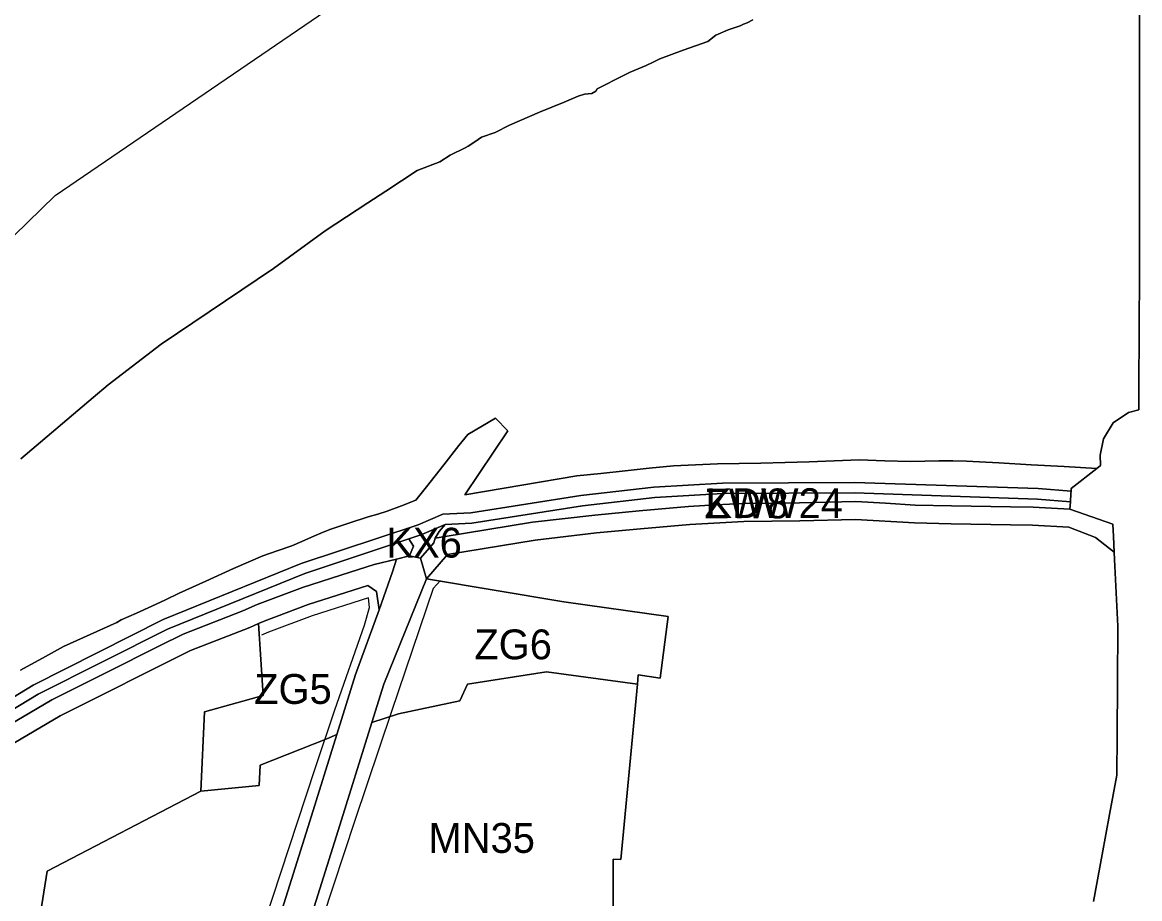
# Model space of a CAD drawing. Extents: x 7428841 to 7433518, y 5545054 to 5546840.
# Drawn here: x 7431568.9 to 7431943.4, y 5546261.6 to 5546555.3 of the extents above; entities that cross this region are included whole.
import ezdxf

# ---------------------------------------------------------------- set-up
doc = ezdxf.new("R2010")
doc.units = 0
for name, color, linetype in [('linie_rozgraniczajace', 7, 'Continuous'), ('linie_zabudowy_nieprzekraczalne', 7, 'Continuous'), ('oznaczenia_przeznaczen', 7, 'Continuous')]:
    doc.layers.add(name, color=color, linetype=linetype)

msp = doc.modelspace()

# ---------------------------------------------------------------- linework, layer by layer
at = {"layer": 'linie_rozgraniczajace'}
for points in [[(7431943.41, 5546570.58), (7431943.39, 5546479.9), (7431943.39, 5546471.91), (7431943.14, 5546432.52), (7431943.09, 5546425.43), (7431939.66, 5546424.55), (7431934.53, 5546421.02), (7431931.32, 5546415.69), (7431930.22, 5546410.24), (7431930.29, 5546406.73), (7431929.09, 5546405.79), (7431918.07, 5546406.42), (7431907.03, 5546407.04), (7431896.21, 5546407.64), (7431885.38, 5546408.23), (7431880.75, 5546408.3), (7431876.11, 5546408.38), (7431871.37, 5546408.22), (7431866.64, 5546408.06), (7431858, 5546408.34), (7431849.37, 5546408.62), (7431841, 5546408.3), (7431832.64, 5546407.97), (7431824.54, 5546407.78), (7431816.43, 5546407.6), (7431809.17, 5546407.44), (7431801.9, 5546407.29), (7431787.12, 5546406.69), (7431779.01, 5546405.84), (7431770.91, 5546404.99), (7431762.81, 5546404.14), (7431754.7, 5546403.29), (7431736.26, 5546400.2), (7431717.21, 5546396.99), (7431731.59, 5546418.42), (7431727.51, 5546422.65)], [(7431927.98, 5546260.72), (7431930.86, 5546276.41), (7431933.32, 5546289.8), (7431935.75, 5546303), (7431935.84, 5546316.43), (7431935.97, 5546333.93), (7431936.11, 5546352.9), (7431934.98, 5546375.22), (7431934.85, 5546377.76), (7431934.59, 5546382.97), (7431934.38, 5546387.09), (7431920.05, 5546392.14), (7431920.2, 5546394.64), (7431920.37, 5546397.33), (7431920.42, 5546398.14), (7431920.47, 5546399.05), (7431929.09, 5546405.79), (7431930.29, 5546406.73), (7431930.22, 5546410.24), (7431931.32, 5546415.69), (7431934.53, 5546421.02), (7431939.66, 5546424.55), (7431943.09, 5546425.43), (7431943.14, 5546432.52), (7431943.39, 5546471.91), (7431943.39, 5546479.9), (7431943.41, 5546570.58)], [(7431294.78, 5546263.35), (7431363.88, 5546310.19), (7431455.51, 5546382.62), (7431520.49, 5546439.04), (7431561.48, 5546479.2), (7431579.86, 5546497.22), (7431670.62, 5546559.16)], [(7431690.69, 5546498.7), (7431701.25, 5546505.59), (7431708.87, 5546508.49), (7431712.25, 5546510.78), (7431717.29, 5546513.26), (7431718.35, 5546513.78), (7431720.58, 5546515.26), (7431722.81, 5546516.75), (7431727.41, 5546518.34), (7431732.16, 5546520.78), (7431742.28, 5546525.11), (7431750.45, 5546528.51), (7431755.24, 5546530.47), (7431757.34, 5546531.16), (7431758.53, 5546531.28), (7431759.72, 5546531.41), (7431761.16, 5546532.24), (7431761.61, 5546532.95), (7431763.98, 5546534.17), (7431767.92, 5546536.19), (7431772.63, 5546538.61), (7431773.98, 5546539.15), (7431776.69, 5546540.25), (7431778.04, 5546540.8), (7431780.3, 5546541.9), (7431782.56, 5546543.01), (7431790.43, 5546545.88), (7431798.63, 5546548.86), (7431801.32, 5546551.01), (7431805.44, 5546552.71), (7431808.48, 5546553.78), (7431809.5, 5546554.14), (7431810.65, 5546554.63), (7431811.81, 5546555.11), (7431813.77, 5546556.09)], [(7431813.77, 5546556.09), (7431811.81, 5546555.11), (7431810.65, 5546554.63), (7431809.5, 5546554.14), (7431808.48, 5546553.78), (7431805.44, 5546552.71), (7431801.32, 5546551.01), (7431798.63, 5546548.86)], [(7431798.63, 5546548.86), (7431790.43, 5546545.88), (7431782.56, 5546543.01), (7431780.3, 5546541.9), (7431778.04, 5546540.8), (7431776.69, 5546540.25), (7431773.98, 5546539.15), (7431772.63, 5546538.61), (7431767.92, 5546536.19), (7431763.98, 5546534.17), (7431761.61, 5546532.95), (7431761.16, 5546532.24), (7431759.72, 5546531.41), (7431758.53, 5546531.28), (7431757.34, 5546531.16), (7431755.24, 5546530.47), (7431750.45, 5546528.51), (7431742.28, 5546525.11), (7431732.16, 5546520.78), (7431727.41, 5546518.34), (7431722.81, 5546516.75), (7431720.58, 5546515.26), (7431718.35, 5546513.78), (7431717.29, 5546513.26), (7431712.25, 5546510.78), (7431708.87, 5546508.49), (7431701.25, 5546505.59), (7431690.69, 5546498.7), (7431684.66, 5546494.77), (7431670.38, 5546485.45), (7431653.09, 5546472.82), (7431615.39, 5546447.39), (7431597.62, 5546433.81), (7431592.58, 5546429.54), (7431568.37, 5546408.98)], [(7431568.37, 5546408.98), (7431592.58, 5546429.54), (7431597.62, 5546433.81), (7431615.39, 5546447.39), (7431653.09, 5546472.82), (7431670.38, 5546485.45), (7431684.66, 5546494.77), (7431690.69, 5546498.7)], [(7431727.51, 5546422.65), (7431718.16, 5546417.17), (7431715.2, 5546413.45), (7431710.12, 5546406.95), (7431704.38, 5546399.66), (7431700.75, 5546395.15), (7431695.97, 5546393.29), (7431691.2, 5546391.43), (7431688, 5546390.51), (7431684.79, 5546389.59), (7431678.36, 5546387.46), (7431671.92, 5546385.32), (7431668.88, 5546384.05), (7431665.85, 5546382.78), (7431662.54, 5546381.33), (7431659.24, 5546379.87), (7431654.34, 5546378.17), (7431649.45, 5546376.47), (7431639.63, 5546372.2), (7431630.41, 5546368.02), (7431621.47, 5546363.96), (7431616.89, 5546361.8), (7431612.31, 5546359.65), (7431607.14, 5546357.33), (7431601.97, 5546355), (7431600.56, 5546354.16), (7431591.63, 5546350.13), (7431582.71, 5546346.1), (7431576.66, 5546342.76), (7431568.28, 5546338.24)], [(7431568.28, 5546338.24), (7431576.66, 5546342.76), (7431582.71, 5546346.1), (7431591.63, 5546350.13), (7431600.56, 5546354.16), (7431601.97, 5546355), (7431607.14, 5546357.33), (7431612.31, 5546359.65), (7431616.89, 5546361.8), (7431621.47, 5546363.96), (7431630.41, 5546368.02), (7431639.63, 5546372.2), (7431649.45, 5546376.47), (7431654.34, 5546378.17), (7431659.24, 5546379.87), (7431662.54, 5546381.33), (7431665.85, 5546382.78), (7431668.88, 5546384.05), (7431671.92, 5546385.32), (7431678.36, 5546387.46), (7431684.79, 5546389.59), (7431688, 5546390.51), (7431691.2, 5546391.43), (7431695.97, 5546393.29), (7431700.75, 5546395.15), (7431704.38, 5546399.66), (7431710.12, 5546406.95), (7431715.2, 5546413.45), (7431718.16, 5546417.17), (7431727.51, 5546422.65), (7431731.59, 5546418.42), (7431717.21, 5546396.99), (7431736.26, 5546400.2), (7431754.7, 5546403.29), (7431762.81, 5546404.14), (7431770.91, 5546404.99), (7431779.01, 5546405.84), (7431787.12, 5546406.69), (7431801.9, 5546407.29), (7431809.17, 5546407.44), (7431816.43, 5546407.6), (7431824.54, 5546407.78), (7431832.64, 5546407.97), (7431841, 5546408.3), (7431849.37, 5546408.62), (7431858, 5546408.34), (7431866.64, 5546408.06), (7431871.37, 5546408.22), (7431876.11, 5546408.38), (7431880.75, 5546408.3), (7431885.38, 5546408.23), (7431896.21, 5546407.64), (7431907.03, 5546407.04), (7431918.07, 5546406.42), (7431929.09, 5546405.79), (7431920.47, 5546399.05), (7431920.42, 5546398.14), (7431909.37, 5546399.02), (7431847.87, 5546401.12), (7431803.57, 5546400.9), (7431780.54, 5546399.55), (7431756.14, 5546396.71), (7431719.21, 5546390.93), (7431709.83, 5546390.41)], [(7431338.24, 5546174.92), (7431376.11, 5546195.36), (7431390.44, 5546204), (7431427.33, 5546229.51), (7431455.1, 5546251.84), (7431501.9, 5546288.09), (7431538.36, 5546313.12), (7431556.69, 5546323.61), (7431572.45, 5546333.17), (7431616.06, 5546355.16), (7431662.33, 5546373.92), (7431701.56, 5546386.93), (7431709.83, 5546390.41), (7431719.21, 5546390.93), (7431756.14, 5546396.71), (7431780.54, 5546399.55), (7431803.57, 5546400.9), (7431847.87, 5546401.12), (7431909.37, 5546399.02)], [(7431909.37, 5546399.02), (7431920.42, 5546398.14), (7431920.37, 5546397.33), (7431920.2, 5546394.64), (7431909.17, 5546395.53), (7431847.82, 5546397.62), (7431803.68, 5546397.41), (7431780.84, 5546396.06), (7431756.62, 5546393.25), (7431719.58, 5546387.45), (7431710.63, 5546386.95), (7431702.79, 5546383.65), (7431698.44, 5546382.21), (7431663.54, 5546370.63), (7431617.51, 5546351.97), (7431574.15, 5546330.11), (7431558.47, 5546320.6), (7431540.22, 5546310.15), (7431503.96, 5546285.26), (7431457.27, 5546249.09), (7431429.43, 5546226.71), (7431392.34, 5546201.05), (7431377.84, 5546192.32), (7431339.83, 5546171.8)], [(7431709.83, 5546390.41), (7431701.56, 5546386.93), (7431662.33, 5546373.92), (7431616.06, 5546355.16), (7431572.45, 5546333.17), (7431556.69, 5546323.61), (7431538.36, 5546313.12), (7431501.9, 5546288.09), (7431455.1, 5546251.84), (7431427.33, 5546229.51), (7431390.44, 5546204), (7431376.11, 5546195.36), (7431338.24, 5546174.92)], [(7431766.85, 5546234.13), (7431766.93, 5546274.9), (7431769.53, 5546274.71), (7431775.08, 5546333.48), (7431775.27, 5546336.6), (7431782.71, 5546335.49), (7431785.37, 5546356.19), (7431750.43, 5546361.07), (7431704.3, 5546368.77), (7431711.37, 5546376.98), (7431740.78, 5546381.8), (7431761.35, 5546384.22), (7431776.14, 5546385.58), (7431792.58, 5546387.05), (7431810.74, 5546388.05), (7431829.51, 5546388.23), (7431848.16, 5546388.68), (7431867.94, 5546387.51), (7431880.26, 5546387.24), (7431900.07, 5546386.91), (7431907.52, 5546386.83), (7431919.71, 5546386.15), (7431928.6, 5546382.67), (7431934.85, 5546377.76), (7431934.98, 5546375.22), (7431936.11, 5546352.9), (7431935.97, 5546333.93), (7431935.84, 5546316.43), (7431935.75, 5546303), (7431933.32, 5546289.8), (7431930.86, 5546276.41), (7431927.98, 5546260.72)], [(7431558.47, 5546320.6), (7431574.15, 5546330.11), (7431617.51, 5546351.97), (7431663.54, 5546370.63), (7431698.44, 5546382.21), (7431700.01, 5546379.69), (7431698.6, 5546376.45), (7431694.32, 5546375.42), (7431686.84, 5546373.61), (7431678.81, 5546371.04), (7431662.75, 5546365.88), (7431647.63, 5546360.19), (7431642.78, 5546358.07), (7431622.81, 5546350.25), (7431614.9, 5546346.29), (7431596.82, 5546337.25), (7431578.74, 5546328.21), (7431573.88, 5546325.35), (7431543.41, 5546307.44)], [(7431543.41, 5546307.44), (7431573.88, 5546325.35), (7431578.74, 5546328.21), (7431596.82, 5546337.25), (7431614.9, 5546346.29), (7431622.81, 5546350.25), (7431642.78, 5546358.07), (7431647.63, 5546360.19), (7431662.75, 5546365.88), (7431678.81, 5546371.04), (7431686.84, 5546373.61), (7431694.32, 5546375.42), (7431692.98, 5546371.13), (7431688.5, 5546358.38), (7431687.59, 5546364.53), (7431684.65, 5546366.61), (7431664.73, 5546360.21), (7431649.89, 5546354.62), (7431648.04, 5546353.82), (7431645.08, 5546352.52), (7431625.25, 5546344.76), (7431581.61, 5546322.94), (7431546.61, 5546302.36)], [(7431649.87, 5546238.51), (7431665.23, 5546287.62), (7431674.31, 5546316.64), (7431680.59, 5546336.73), (7431688.5, 5546358.38), (7431692.98, 5546371.13), (7431694.32, 5546375.42), (7431698.6, 5546376.45), (7431702.32, 5546375.67), (7431704.3, 5546368.77), (7431697.17, 5546351.12), (7431690.05, 5546333.48), (7431686.02, 5546320.6), (7431674.71, 5546284.42), (7431660.04, 5546237.52)], [(7431546.61, 5546302.36), (7431581.61, 5546322.94), (7431625.25, 5546344.76), (7431645.08, 5546352.52), (7431648.04, 5546353.82), (7431649.59, 5546329.66), (7431629.92, 5546324.21), (7431628.71, 5546297.68), (7431577.2, 5546270.87), (7431573.01, 5546244.86), (7431569.77, 5546227.41), (7431583.51, 5546224.99), (7431590.89, 5546221.81), (7431603.1, 5546208.27), (7431498.28, 5546137.46)], [(7431498.28, 5546137.46), (7431603.1, 5546208.27), (7431590.89, 5546221.81), (7431583.51, 5546224.99), (7431569.77, 5546227.41), (7431573.01, 5546244.86), (7431577.2, 5546270.87), (7431628.71, 5546297.68), (7431648.22, 5546299.54), (7431648.57, 5546306.31), (7431670.95, 5546315.15), (7431674.31, 5546316.64), (7431665.23, 5546287.62), (7431649.87, 5546238.51), (7431645.77, 5546226.85), (7431641.66, 5546215.2), (7431631.7, 5546167.48), (7431625.03, 5546159.14), (7431616.9, 5546155.4), (7431607.47, 5546150.42), (7431598.03, 5546145.44), (7431580.23, 5546138.04), (7431562.44, 5546130.63)]]:
    msp.add_lwpolyline(points, dxfattribs=at)
for points in [[(7431707.29, 5546382.39), (7431708.61, 5546384.67), (7431710.63, 5546386.95), (7431719.58, 5546387.45), (7431756.62, 5546393.25), (7431780.84, 5546396.06), (7431803.68, 5546397.41), (7431847.82, 5546397.62), (7431909.17, 5546395.53), (7431920.2, 5546394.64), (7431920.05, 5546392.14), (7431907.72, 5546392.83), (7431900.15, 5546392.9), (7431880.38, 5546393.24), (7431868.18, 5546393.5), (7431858.22, 5546394.1), (7431848.26, 5546394.69), (7431838.83, 5546394.46), (7431829.41, 5546394.23), (7431819.98, 5546394.14), (7431810.55, 5546394.05), (7431801.35, 5546393.54), (7431792.15, 5546393.04), (7431775.59, 5546391.56), (7431760.73, 5546390.18), (7431739.94, 5546387.74), (7431709.97, 5546382.83)], [(7431702.32, 5546375.67), (7431706.83, 5546380.9), (7431707.29, 5546382.39), (7431709.97, 5546382.83), (7431739.94, 5546387.74), (7431760.73, 5546390.18), (7431775.59, 5546391.56), (7431792.15, 5546393.04), (7431801.35, 5546393.54), (7431810.55, 5546394.05), (7431819.98, 5546394.14), (7431829.41, 5546394.23), (7431838.83, 5546394.46), (7431848.26, 5546394.69), (7431858.22, 5546394.1), (7431868.18, 5546393.5), (7431880.38, 5546393.24), (7431900.15, 5546392.9), (7431907.72, 5546392.83), (7431920.05, 5546392.14), (7431934.38, 5546387.09), (7431934.59, 5546382.97), (7431934.85, 5546377.76), (7431928.6, 5546382.67), (7431919.71, 5546386.15), (7431907.52, 5546386.83), (7431900.07, 5546386.91), (7431880.26, 5546387.24), (7431867.94, 5546387.51), (7431848.16, 5546388.68), (7431829.51, 5546388.23), (7431810.74, 5546388.05), (7431792.58, 5546387.05), (7431776.14, 5546385.58), (7431761.35, 5546384.22), (7431740.78, 5546381.8), (7431711.37, 5546376.98), (7431704.3, 5546368.77)], [(7431698.6, 5546376.45), (7431700.01, 5546379.69), (7431698.44, 5546382.21), (7431702.79, 5546383.65), (7431710.63, 5546386.95), (7431708.61, 5546384.67), (7431707.29, 5546382.39), (7431706.83, 5546380.9), (7431702.32, 5546375.67)], [(7431686.02, 5546320.6), (7431690.05, 5546333.48), (7431697.17, 5546351.12), (7431704.3, 5546368.77), (7431750.43, 5546361.07), (7431785.37, 5546356.19), (7431782.71, 5546335.49), (7431775.27, 5546336.6), (7431775.08, 5546333.48), (7431744.61, 5546337.67), (7431718.05, 5546333.49), (7431715.52, 5546327.92), (7431694.98, 5546323.51)], [(7431628.71, 5546297.68), (7431629.92, 5546324.21), (7431649.59, 5546329.66), (7431648.04, 5546353.82), (7431649.89, 5546354.62), (7431664.73, 5546360.21), (7431684.65, 5546366.61), (7431687.59, 5546364.53), (7431688.5, 5546358.38), (7431680.59, 5546336.73), (7431674.31, 5546316.64), (7431670.95, 5546315.15), (7431648.57, 5546306.31), (7431648.22, 5546299.54)], [(7431660.04, 5546237.52), (7431674.71, 5546284.42), (7431686.02, 5546320.6), (7431694.98, 5546323.51), (7431715.52, 5546327.92), (7431718.05, 5546333.49), (7431744.61, 5546337.67), (7431775.08, 5546333.48), (7431769.53, 5546274.71), (7431766.93, 5546274.9), (7431766.85, 5546234.13), (7431745.12, 5546233.11), (7431744.94, 5546240.93), (7431734.58, 5546240.75), (7431730.78, 5546237.16), (7431725.33, 5546236.85), (7431719.88, 5546236.53), (7431713.11, 5546235.93), (7431706.33, 5546235.33), (7431675.2, 5546232.86), (7431663.77, 5546232.04)]]:
    msp.add_lwpolyline(points, close=True, dxfattribs=at)
at = {"layer": 'linie_zabudowy_nieprzekraczalne'}
for points in [[(7431709.03, 5546368.18), (7431706.62, 5546365.53)], [(7431706.62, 5546365.53), (7431692.58, 5546324.35), (7431680.29, 5546287.84), (7431669.44, 5546255), (7431665.05, 5546241.43), (7431664, 5546238.76)], [(7431628.05, 5546169.3), (7431633.33, 5546197.4), (7431637.47, 5546215.13), (7431641.6, 5546227.85), (7431664.06, 5546296.07), (7431667.14, 5546305.63), (7431673.68, 5546324.85), (7431683.59, 5546353.3), (7431685.3, 5546359.17), (7431684.87, 5546362.45)], [(7431684.87, 5546362.45), (7431666.04, 5546356.44), (7431651.4, 5546350.92), (7431649, 5546349.87)]]:
    msp.add_lwpolyline(points, dxfattribs=at)

# ---------------------------------------------------------------- texts
at = {"layer": 'oznaczenia_przeznaczen'}
for s, p in [('ZW8', (7431797.52, 5546389.05)), ('KDW24', (7431797.89, 5546389.14)), ('KX6', (7431690.92, 5546375.91)), ('ZG6', (7431720.4, 5546341.83)), ('ZG5', (7431646.58, 5546326.89)), ('MN35', (7431705.03, 5546276.97))]:
    msp.add_text(s, height=10, dxfattribs=at).set_placement(p)

doc.saveas('drawing.dxf')
